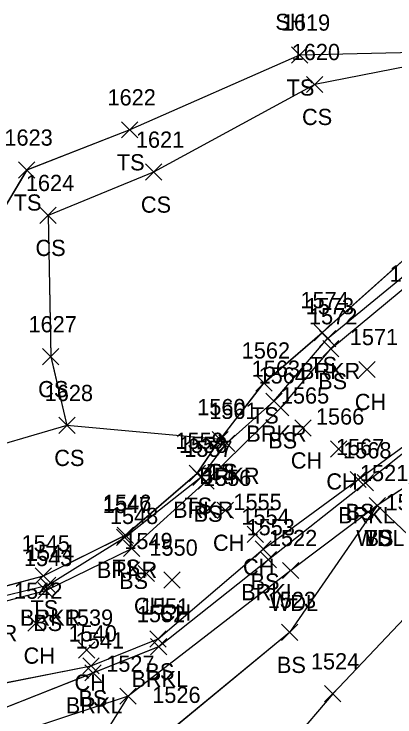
# Model space of a CAD drawing. Extents: x 1415642 to 1422021, y 544543 to 547232.
# Drawn here: x 1416043.1 to 1416090, y 546718.3 to 546804.9 of the extents above; entities that cross this region are included whole.
import ezdxf

# ---------------------------------------------------------------- set-up
doc = ezdxf.new("R2010")
doc.units = 0
for name, color, linetype in [('L_A', 7, 'Continuous'), ('L_I', 7, 'Continuous'), ('L_TIC', 7, 'Continuous'), ('LAWA', 7, 'Continuous'), ('LAWE', 7, 'Continuous'), ('LELB', 7, 'Continuous'), ('LFNC', 7, 'Continuous')]:
    doc.layers.add(name, color=color, linetype=linetype)

msp = doc.modelspace()

# ---------------------------------------------------------------- linework, layer by layer
at = {"layer": 'L_TIC'}
for points in [[(1416077.212, 546798.853), (1416079.212, 546800.853)], [(1416079.212, 546798.853), (1416077.212, 546800.853)], [(1416079.073, 546795.226), (1416081.073, 546797.226)], [(1416081.073, 546795.226), (1416079.073, 546797.226)], [(1416056.31, 546789.638), (1416058.31, 546791.638)], [(1416058.31, 546789.638), (1416056.31, 546791.638)], [(1416043.618, 546784.685), (1416045.618, 546786.685)], [(1416045.618, 546784.685), (1416043.618, 546786.685)], [(1416059.239, 546784.43), (1416061.239, 546786.43)], [(1416061.239, 546784.43), (1416059.239, 546786.43)], [(1416046.261, 546779.092), (1416048.261, 546781.092)], [(1416048.261, 546779.092), (1416046.261, 546781.092)], [(1416080.012, 546764.66), (1416082.012, 546766.66)], [(1416082.012, 546764.66), (1416080.012, 546766.66)], [(1416080.661, 546763.919), (1416082.661, 546765.919)], [(1416082.661, 546763.919), (1416080.661, 546765.919)], [(1416081.063, 546762.674), (1416083.063, 546764.674)], [(1416083.063, 546762.674), (1416081.063, 546764.674)], [(1416046.587, 546761.691), (1416048.587, 546763.691)], [(1416048.587, 546761.691), (1416046.587, 546763.691)], [(1416085.523, 546760.112), (1416087.523, 546762.112)], [(1416087.523, 546760.112), (1416085.523, 546762.112)], [(1416072.833, 546758.454), (1416074.833, 546760.454)], [(1416074.833, 546758.454), (1416072.833, 546760.454)], [(1416074.059, 546756.214), (1416076.059, 546758.214)], [(1416076.059, 546756.214), (1416074.059, 546758.214)], [(1416074.911, 546755.381), (1416076.911, 546757.381)], [(1416076.911, 546755.381), (1416074.911, 546757.381)], [(1416048.577, 546753.218), (1416050.577, 546755.218)], [(1416050.577, 546753.218), (1416048.577, 546755.218)], [(1416048.577, 546753.218), (1416050.577, 546755.218)], [(1416050.577, 546753.218), (1416048.577, 546755.218)], [(1416077.649, 546752.905), (1416079.649, 546754.905)], [(1416079.649, 546752.905), (1416077.649, 546754.905)], [(1416067.435, 546751.479), (1416069.435, 546753.479)], [(1416069.435, 546751.479), (1416067.435, 546753.479)], [(1416067.435, 546751.479), (1416069.435, 546753.479)], [(1416069.435, 546751.479), (1416067.435, 546753.479)], [(1416068.262, 546751.019), (1416070.262, 546753.019)], [(1416070.262, 546751.019), (1416068.262, 546753.019)], [(1416082.018, 546750.318), (1416084.018, 546752.318)], [(1416084.018, 546750.318), (1416082.018, 546752.318)], [(1416064.626, 546747.326), (1416066.626, 546749.326)], [(1416066.626, 546747.326), (1416064.626, 546749.326)], [(1416065.054, 546746.833), (1416067.054, 546748.833)], [(1416067.054, 546746.833), (1416065.054, 546748.833)], [(1416065.711, 546746.347), (1416067.711, 546748.347)], [(1416067.711, 546746.347), (1416065.711, 546748.347)], [(1416084.425, 546746.563), (1416086.425, 546748.563)], [(1416086.425, 546746.563), (1416084.425, 546748.563)], [(1416085.319, 546746.157), (1416087.319, 546748.157)], [(1416087.319, 546746.157), (1416085.319, 546748.157)], [(1416068.066, 546742.765), (1416070.066, 546744.765)], [(1416070.066, 546742.765), (1416068.066, 546744.765)], [(1416086.771, 546743.353), (1416088.771, 546745.353)], [(1416088.771, 546743.353), (1416086.771, 546745.353)], [(1416086.771, 546743.353), (1416088.771, 546745.353)], [(1416088.771, 546743.353), (1416086.771, 546745.353)], [(1416086.771, 546743.353), (1416088.771, 546745.353)], [(1416088.771, 546743.353), (1416086.771, 546745.353)], [(1416055.672, 546739.419), (1416057.672, 546741.419)], [(1416057.672, 546739.419), (1416055.672, 546741.419)], [(1416055.761, 546739.689), (1416057.761, 546741.689)], [(1416057.761, 546739.689), (1416055.761, 546741.689)], [(1416071.76, 546739.793), (1416073.76, 546741.793)], [(1416073.76, 546739.793), (1416071.76, 546741.793)], [(1416056.557, 546738.074), (1416058.557, 546740.074)], [(1416058.557, 546738.074), (1416056.557, 546740.074)], [(1416072.737, 546737.984), (1416074.737, 546739.984)], [(1416074.737, 546737.984), (1416072.737, 546739.984)], [(1416073.377, 546736.683), (1416075.377, 546738.683)], [(1416075.377, 546736.683), (1416073.377, 546738.683)], [(1416058.338, 546734.982), (1416060.338, 546736.982)], [(1416060.338, 546734.982), (1416058.338, 546736.982)], [(1416076.131, 546735.348), (1416078.131, 546737.348)], [(1416078.131, 546735.348), (1416076.131, 546737.348)], [(1416045.683, 546734.69), (1416047.683, 546736.69)], [(1416047.683, 546734.69), (1416045.683, 546736.69)], [(1416061.506, 546734.168), (1416063.506, 546736.168)], [(1416063.506, 546734.168), (1416061.506, 546736.168)], [(1416046.212, 546733.536), (1416048.212, 546735.536)], [(1416048.212, 546733.536), (1416046.212, 546735.536)], [(1416045.981, 546732.886), (1416047.981, 546734.886)], [(1416047.981, 546732.886), (1416045.981, 546734.886)], [(1416044.754, 546728.857), (1416046.754, 546730.857)], [(1416046.754, 546728.857), (1416044.754, 546730.857)], [(1416075.983, 546727.719), (1416077.983, 546729.719)], [(1416077.983, 546727.719), (1416075.983, 546729.719)], [(1416059.793, 546726.919), (1416061.793, 546728.919)], [(1416061.793, 546726.919), (1416059.793, 546728.919)], [(1416051.02, 546725.548), (1416053.02, 546727.548)], [(1416053.02, 546725.548), (1416051.02, 546727.548)], [(1416059.875, 546725.975), (1416061.875, 546727.975)], [(1416061.875, 546725.975), (1416059.875, 546727.975)], [(1416051.55, 546723.596), (1416053.55, 546725.596)], [(1416053.55, 546723.596), (1416051.55, 546725.596)], [(1416051.784, 546722.735), (1416053.784, 546724.735)], [(1416053.784, 546722.735), (1416051.784, 546724.735)], [(1416081.302, 546720.158), (1416083.302, 546722.158)], [(1416083.302, 546720.158), (1416081.302, 546722.158)], [(1416056.108, 546719.869), (1416058.108, 546721.869)], [(1416058.108, 546719.869), (1416056.108, 546721.869)], [(1416056.108, 546719.869), (1416058.108, 546721.869)], [(1416058.108, 546719.869), (1416056.108, 546721.869)]]:
    msp.add_lwpolyline(points, dxfattribs=at)
at = {"layer": 'LAWA'}
for points in [[(1416189.468, 546748.093), (1416170.483, 546756.813), (1416159.398, 546761.07), (1416158.818, 546764.495), (1416158.5, 546767.312), (1416157.339, 546771.4), (1416149.111, 546783.522), (1416143.568, 546776.625), (1416135.571, 546781.553), (1416136.009, 546776.955), (1416135.395, 546775.051), (1416133.212, 546773.698), (1416124.824, 546771.254), (1416110.474, 546763.899), (1416099.189, 546751.925), (1416087.771, 546744.353), (1416077.131, 546736.348), (1416057.108, 546720.869), (1416047.173, 546704.924)], [(1416189.464, 546748.092), (1416170.487, 546756.813), (1416159.394, 546761.071), (1416158.815, 546764.495), (1416158.505, 546767.312), (1416157.342, 546771.4), (1416149.113, 546783.521), (1416143.565, 546776.626), (1416135.574, 546781.553), (1416136.011, 546776.955), (1416135.402, 546775.05), (1416133.216, 546773.698), (1416124.826, 546771.255), (1416110.476, 546763.9), (1416099.195, 546751.924), (1416087.779, 546744.35), (1416077.137, 546736.347), (1416057.114, 546720.867), (1416047.178, 546704.926)]]:
    msp.add_lwpolyline(points, dxfattribs=at)
at = {"layer": 'LAWE'}
for points in [[(1416023.555, 546732.652), (1416039.435, 546732.637), (1416047.212, 546734.536), (1416056.672, 546740.419), (1416066.054, 546747.833), (1416069.262, 546752.019), (1416075.059, 546757.214), (1416081.661, 546764.919), (1416099.922, 546779.935), (1416116.018, 546793.533), (1416127.694, 546798.829)], [(1416023.56, 546732.655), (1416039.44, 546732.638), (1416047.218, 546734.533), (1416056.676, 546740.42), (1416066.062, 546747.829), (1416069.268, 546752.017), (1416075.064, 546757.213), (1416081.67, 546764.916), (1416099.925, 546779.935), (1416116.022, 546793.533), (1416127.702, 546798.828)], [(1416039.047, 546718.337), (1416052.784, 546723.735), (1416060.875, 546726.975), (1416074.377, 546737.683), (1416086.319, 546747.157), (1416093.425, 546752.758), (1416101.98, 546759.616), (1416111.397, 546767.511), (1416119.583, 546772.235), (1416127.403, 546776.082), (1416128.271, 546778.626), (1416129.002, 546780.644), (1416128.144, 546784.491), (1416130.448, 546789.914), (1416132.468, 546795.001), (1416130.863, 546797.224), (1416127.694, 546798.829)], [(1416039.053, 546718.334), (1416052.787, 546723.738), (1416060.879, 546726.977), (1416074.38, 546737.685), (1416086.328, 546747.153), (1416093.43, 546752.758), (1416101.985, 546759.615), (1416111.399, 546767.512), (1416119.591, 546772.233), (1416127.408, 546776.081), (1416128.28, 546778.625), (1416129.011, 546780.643), (1416128.148, 546784.491), (1416130.455, 546789.913), (1416132.475, 546795.001), (1416130.871, 546797.224), (1416127.702, 546798.828)]]:
    msp.add_lwpolyline(points, dxfattribs=at)
at = {"layer": 'LELB'}
for points in [[(1416145.272, 546792.192), (1416140.825, 546785.479), (1416135.571, 546781.553), (1416134.129, 546786.328), (1416133.182, 546791.545), (1416133.267, 546797.305), (1416128.672, 546801.948), (1416121.917, 546800.589), (1416115.746, 546796.749), (1416101.262, 546800.374), (1416080.073, 546796.226), (1416060.239, 546785.43), (1416047.261, 546780.092), (1416047.587, 546762.691), (1416049.577, 546754.218), (1416036.938, 546750.513), (1416008.63, 546746.216)], [(1416145.276, 546792.192), (1416140.832, 546785.478), (1416135.574, 546781.553), (1416134.133, 546786.328), (1416133.185, 546791.545), (1416133.273, 546797.304), (1416128.676, 546801.948), (1416121.918, 546800.589), (1416115.751, 546796.748), (1416101.27, 546800.373), (1416080.083, 546796.225), (1416060.246, 546785.429), (1416047.263, 546780.095), (1416047.594, 546762.689), (1416049.581, 546754.219), (1416036.944, 546750.511), (1416008.636, 546746.22)], [(1416101.262, 546800.374), (1416078.212, 546799.853), (1416057.31, 546790.638), (1416044.618, 546785.685), (1416037.497, 546773.762), (1416039.349, 546764.244), (1416031.983, 546754.711), (1416008.63, 546746.216)], [(1416101.27, 546800.373), (1416078.214, 546799.854), (1416057.312, 546790.64), (1416044.625, 546785.682), (1416037.501, 546773.766), (1416039.354, 546764.244), (1416031.987, 546754.714), (1416008.636, 546746.22)], [(1416023.351, 546735.469), (1416038.951, 546733.616), (1416046.683, 546735.69), (1416056.761, 546740.689), (1416065.626, 546748.326), (1416068.435, 546752.479), (1416073.833, 546759.454), (1416081.012, 546765.66), (1416098.794, 546781.576), (1416115.927, 546794.323)], [(1416023.356, 546735.47), (1416038.957, 546733.613), (1416046.689, 546735.687), (1416056.766, 546740.69), (1416065.629, 546748.329), (1416068.442, 546752.477), (1416073.835, 546759.456), (1416081.018, 546765.659), (1416098.798, 546781.576), (1416115.932, 546794.323)], [(1416023.868, 546730.326), (1416039.929, 546732.026), (1416046.981, 546733.886), (1416057.557, 546739.074), (1416066.711, 546747.347), (1416075.911, 546756.381), (1416082.063, 546763.674), (1416101.063, 546779.443), (1416117.288, 546793.166), (1416118.494, 546793.221)], [(1416023.873, 546730.325), (1416039.933, 546732.029), (1416046.987, 546733.882), (1416057.561, 546739.075), (1416066.718, 546747.345), (1416075.919, 546756.377), (1416082.067, 546763.675), (1416101.071, 546779.441), (1416117.289, 546793.167), (1416118.504, 546793.22)], [(1416037.877, 546721.707), (1416052.55, 546724.596), (1416060.793, 546727.919), (1416073.737, 546738.984), (1416085.425, 546747.563), (1416092.766, 546752.935), (1416101.789, 546760.083), (1416110.668, 546768.082), (1416119.329, 546772.875), (1416125.133, 546776.758), (1416125.641, 546785.647), (1416122.227, 546788.667), (1416118.494, 546793.221)], [(1416037.883, 546721.703), (1416052.556, 546724.595), (1416060.799, 546727.917), (1416073.743, 546738.982), (1416085.432, 546747.561), (1416092.771, 546752.934), (1416101.793, 546760.083), (1416110.675, 546768.081), (1416119.331, 546772.875), (1416125.136, 546776.759), (1416125.643, 546785.648), (1416122.228, 546788.667), (1416118.504, 546793.22)], [(1416068.435, 546752.479), (1416049.577, 546754.218)], [(1416068.442, 546752.477), (1416049.581, 546754.219)], [(1416087.771, 546744.353), (1416076.983, 546728.719), (1416062.826, 546717.027)], [(1416087.779, 546744.35), (1416076.99, 546728.717), (1416062.833, 546717.023)], [(1416094.093, 546733.599), (1416091.572, 546740.759), (1416087.771, 546744.353)], [(1416094.099, 546733.598), (1416091.578, 546740.758), (1416087.779, 546744.35)], [(1416057.108, 546720.869), (1416039.042, 546714.911)], [(1416057.114, 546720.867), (1416039.048, 546714.91)]]:
    msp.add_lwpolyline(points, dxfattribs=at)
at = {"layer": 'LFNC'}
for points in [[(1416124.612, 546767.204), (1416114.009, 546753.752), (1416105.919, 546744.351), (1416094.093, 546733.599), (1416082.302, 546721.158), (1416072.387, 546709.508)], [(1416124.618, 546767.203), (1416114.011, 546753.753), (1416105.922, 546744.352), (1416094.099, 546733.598), (1416082.31, 546721.154), (1416072.394, 546709.506)]]:
    msp.add_lwpolyline(points, dxfattribs=at)

# ---------------------------------------------------------------- texts
at = {"layer": 'L_A'}
for s, p in [('SH', (1416075.228, 546802.937)), ('TS', (1416076.621, 546794.853)), ('CS', (1416078.514, 546791.226)), ('TS', (1416055.72, 546785.638)), ('TS', (1416043.027, 546780.685)), ('CS', (1416058.68, 546780.43)), ('CS', (1416045.702, 546775.092)), ('TS', (1416079.422, 546760.66)), ('BRKR', (1416078.252, 546759.919)), ('BS', (1416080.504, 546758.674)), ('CS', (1416046.028, 546757.691)), ('CH', (1416085.011, 546756.112)), ('TS', (1416072.242, 546754.454)), ('BRKR', (1416071.65, 546752.214)), ('BS', (1416074.352, 546751.381)), ('CS', (1416048.018, 546749.218)), ('CS', (1416048.018, 546749.218)), ('CH', (1416077.137, 546748.905)), ('BRKR', (1416065.853, 546747.019)), ('TS', (1416066.845, 546747.479)), ('CS', (1416066.876, 546747.479)), ('CH', (1416081.506, 546746.318)), ('BRKR', (1416062.644, 546742.833)), ('TS', (1416064.036, 546743.326)), ('BS', (1416065.152, 546742.347)), ('BRKL', (1416082.965, 546742.157)), ('BS', (1416083.866, 546742.563)), ('WDL', (1416085.188, 546739.353)), ('TS', (1416086.18, 546739.353)), ('BS', (1416086.212, 546739.353)), ('CH', (1416067.555, 546738.765)), ('CH', (1416071.248, 546735.793)), ('BRKR', (1416053.262, 546735.419)), ('TS', (1416055.171, 546735.689)), ('BS', (1416055.998, 546734.074)), ('BS', (1416072.178, 546733.984)), ('BRKL', (1416071.023, 546732.683)), ('TS', (1416045.092, 546730.69)), ('CH', (1416057.826, 546730.982)), ('WDL', (1416074.549, 546731.348)), ('CH', (1416060.995, 546730.168)), ('BRKR', (1416043.803, 546729.536)), ('BS', (1416045.422, 546728.886)), ('BRKR', (1416036.026, 546727.637)), ('CH', (1416044.242, 546724.857)), ('BS', (1416075.424, 546723.719)), ('BS', (1416059.234, 546722.919)), ('BRKL', (1416057.52, 546721.975)), ('CH', (1416050.508, 546721.548)), ('BS', (1416050.991, 546719.596)), ('BRKL', (1416049.429, 546718.735))]:
    msp.add_text(s, height=2, dxfattribs=at).set_placement(p)
at = {"layer": 'L_I'}
for s, p in [('1619', (1416076.031, 546802.853)), ('1620', (1416077.246, 546799.226)), ('1622', (1416054.57, 546793.638)), ('1623', (1416041.878, 546788.685)), ('1621', (1416058.066, 546788.43)), ('1624', (1416044.52, 546783.092)), ('1579', (1416089.298, 546771.932)), ('1574', (1416078.319, 546768.66)), ('1573', (1416078.968, 546767.919)), ('1572', (1416079.37, 546766.674)), ('1627', (1416044.847, 546765.691)), ('1571', (1416084.397, 546764.112)), ('1562', (1416071.093, 546762.454)), ('1563', (1416072.319, 546760.214)), ('1564', (1416073.171, 546759.381)), ('1628', (1416046.837, 546757.218)), ('1628', (1416046.837, 546757.218)), ('1565', (1416075.909, 546756.905)), ('1560', (1416065.609, 546755.479)), ('1560', (1416065.609, 546755.479)), ('1561', (1416067.089, 546755.019)), ('1566', (1416080.223, 546754.318)), ('1559', (1416062.926, 546751.326)), ('1558', (1416063.361, 546750.833)), ('1567', (1416082.685, 546750.563)), ('1557', (1416064.019, 546750.347)), ('1568', (1416083.579, 546750.157)), ('1521', (1416085.645, 546747.353)), ('1521', (1416085.645, 546747.353)), ('1521', (1416085.645, 546747.353)), ('1556', (1416066.318, 546746.765)), ('1546', (1416054.013, 546743.689)), ('1555', (1416070.067, 546743.793)), ('1520', (1416088.792, 546743.759)), ('1547', (1416053.979, 546743.419)), ('1548', (1416054.864, 546742.074)), ('1554', (1416071.044, 546741.984)), ('1553', (1416071.684, 546740.683)), ('1522', (1416074.438, 546739.348)), ('1545', (1416043.99, 546738.69)), ('1549', (1416056.637, 546738.982)), ('1544', (1416044.519, 546737.536)), ('1550', (1416059.727, 546738.168)), ('1543', (1416044.288, 546736.886)), ('1542', (1416043.061, 546732.857)), ('1523', (1416074.29, 546731.719)), ('1551', (1416058.667, 546730.919)), ('1552', (1416058.182, 546729.975)), ('1539', (1416049.319, 546729.548)), ('1540', (1416049.771, 546727.596)), ('1541', (1416050.658, 546726.735)), ('1527', (1416054.416, 546723.869)), ('1527', (1416054.416, 546723.869)), ('1524', (1416079.609, 546724.158)), ('1526', (1416060.078, 546720.027))]:
    msp.add_text(s, height=2, dxfattribs=at).set_placement(p)

doc.saveas('drawing.dxf')
